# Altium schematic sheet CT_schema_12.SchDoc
size 742 x 377 mm
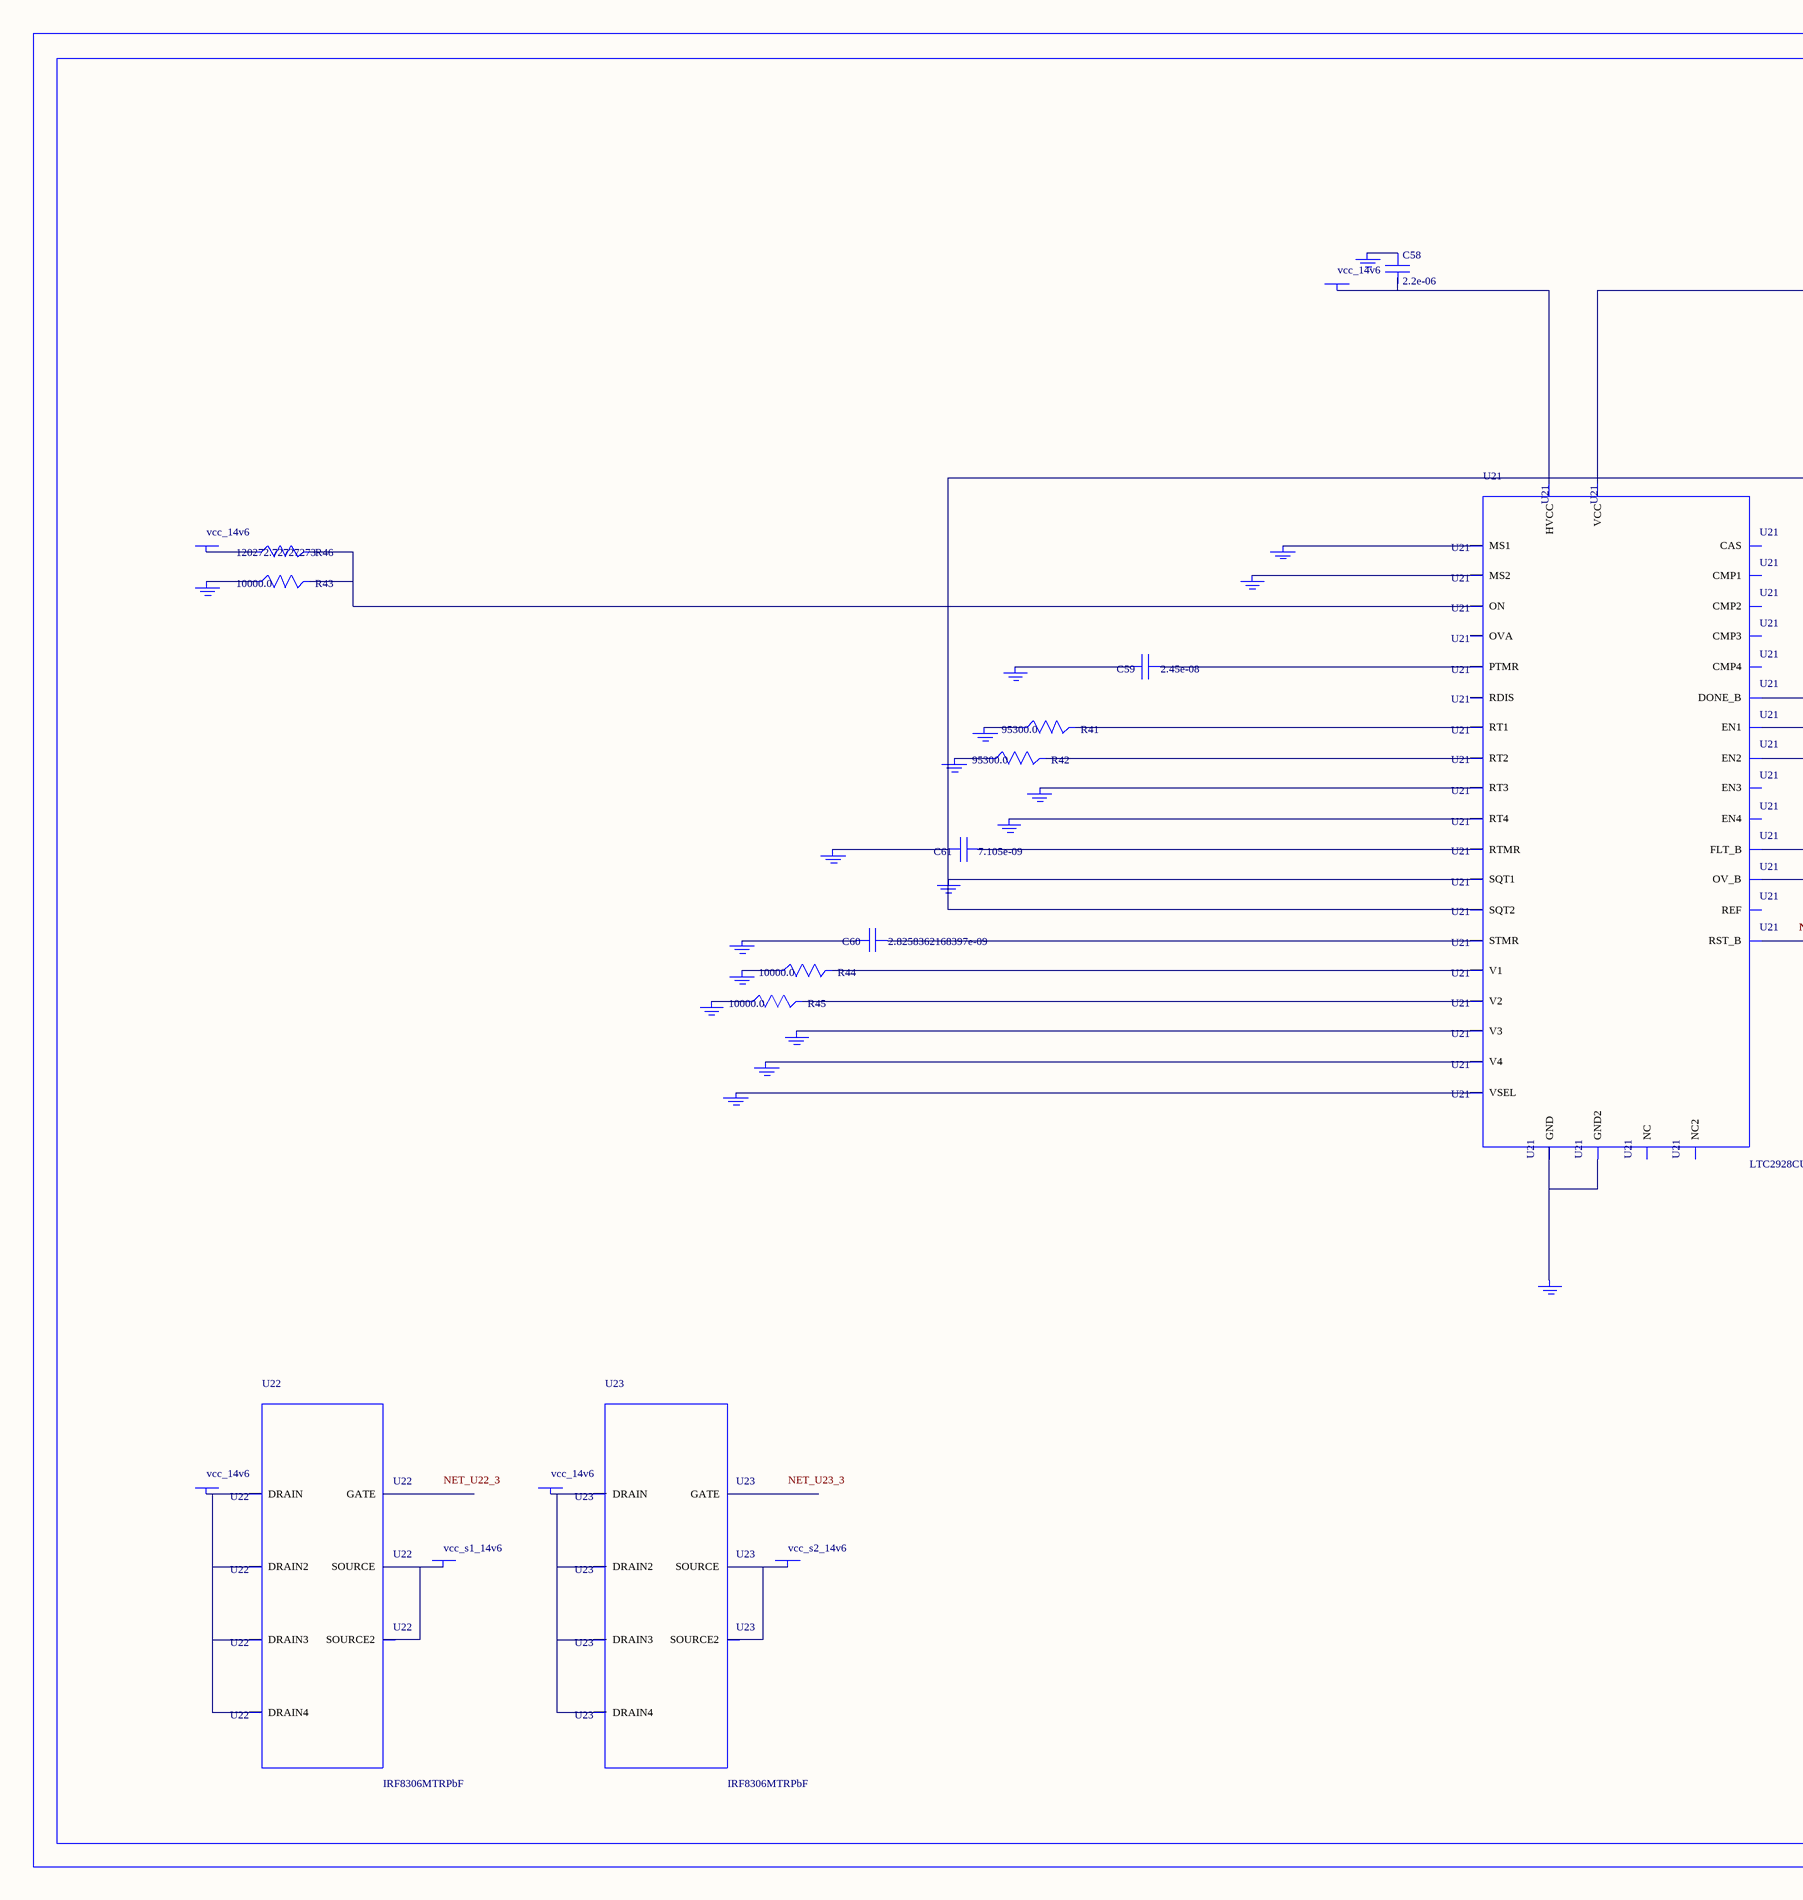
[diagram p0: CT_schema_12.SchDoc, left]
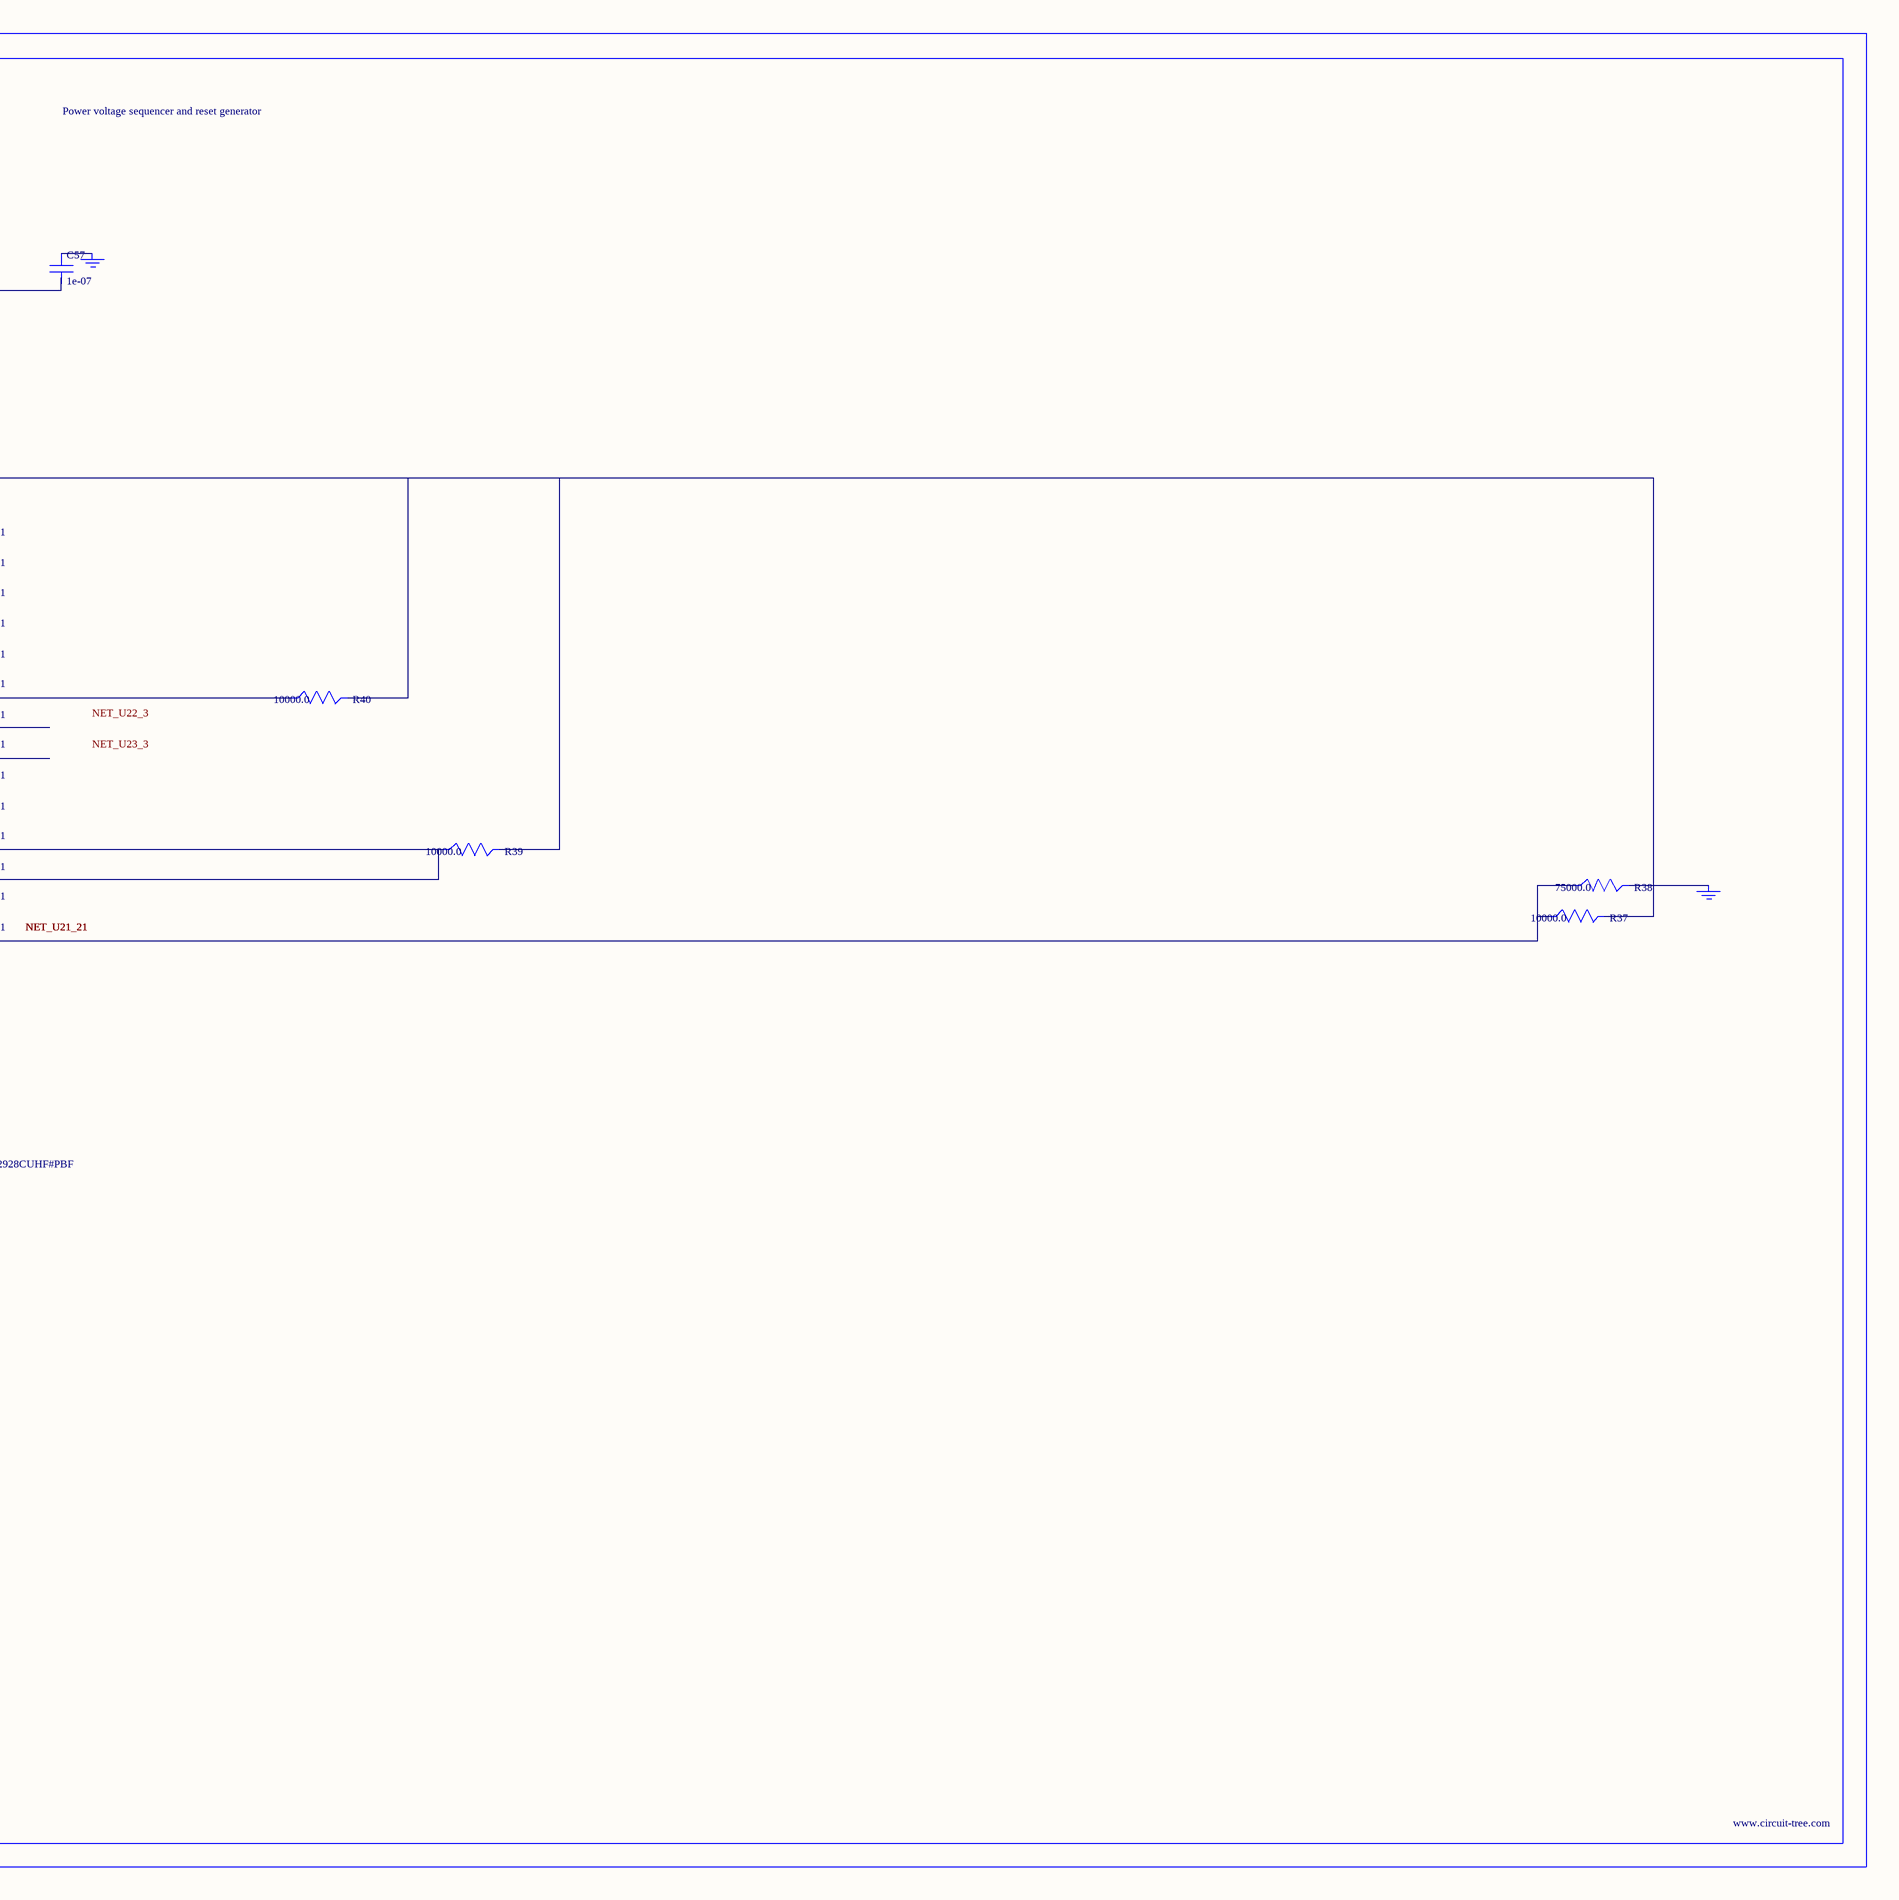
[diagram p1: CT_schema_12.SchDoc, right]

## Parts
BORDER11  (no value)
C57  1e-07  [C0402]
C58  2.2e-06  [C0603]
C59  2.45e-08  [R0603]
C60  2.8258362168397e-09  [R0603]
C61  7.105e-09  [R0603]
GND_INSTANCE_11_0  (no value)
GND_INSTANCE_11_1  (no value)
GND_INSTANCE_11_2  (no value)
GND_INSTANCE_11_3  (no value)
GND_INSTANCE_11_4  (no value)
GND_INSTANCE_11_5  (no value)
GND_INSTANCE_11_6  (no value)
GND_INSTANCE_11_7  (no value)
GND_INSTANCE_11_8  (no value)
GND_INSTANCE_11_9  (no value)
GND_INSTANCE_11_10  (no value)
GND_INSTANCE_11_11  (no value)
GND_INSTANCE_11_12  (no value)
GND_INSTANCE_11_13  (no value)
GND_INSTANCE_11_14  (no value)
GND_INSTANCE_11_15  (no value)
GND_INSTANCE_11_16  (no value)
GND_INSTANCE_11_17  (no value)
GND_INSTANCE_11_18  (no value)
GND_INSTANCE_11_19  (no value)
POWER_INSTANCE_11_0  vcc_14v6
POWER_INSTANCE_11_1  vcc_14v6
POWER_INSTANCE_11_2  vcc_14v6
POWER_INSTANCE_11_3  vcc_s1_14v6
POWER_INSTANCE_11_4  vcc_14v6
POWER_INSTANCE_11_5  vcc_s2_14v6
R37  10000.0  [R0603]
R38  75000.0  [R0603]
R39  10000.0  [R0603]
R40  10000.0  [R0603]
R41  95300.0  [R0603]
R42  95300.0  [R0603]
R43  10000.0  [R0603]
R44  10000.0  [R0603]
R45  10000.0  [R0603]
R46  120272.72727273  [R0603]
U21  LTC2928CUHF#PBF  [QFN-38_UHF]
U22  IRF8306MTRPbF  [IRF8306MTRPBF]
U23  IRF8306MTRPbF  [IRF8306MTRPBF]

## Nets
NetC57_1: C57.1 GND_INSTANCE_11_10.0(GND)
NetC57_2: C57.2 C61.2 GND_INSTANCE_11_5.0(GND) GND_INSTANCE_11_15.0(GND) R37.2 R39.2 R40.2 U21.10(SQT1) U21.11(SQT2) U21.22(VCC)
NetC58_1: C58.1 GND_INSTANCE_11_11.0(GND)
NetC58_2: C58.2 POWER_INSTANCE_11_1.0(PWR) U21.23(HVCC)
NetC59_1: C59.1 U21.27(PTMR)
NetC59_2: C59.2 GND_INSTANCE_11_14.0(GND)
NetC60_1: C60.1 U21.26(STMR)
NetC60_2: C60.2 GND_INSTANCE_11_13.0(GND)
NetC61_1: C61.1 U21.28(RTMR)
NetGND_INSTANCE_11_0_0: GND_INSTANCE_11_0.0(GND) R44.1
NetGND_INSTANCE_11_1_0: GND_INSTANCE_11_1.0(GND) R41.1
NetGND_INSTANCE_11_2_0: GND_INSTANCE_11_2.0(GND) R42.1
NetGND_INSTANCE_11_3_0: GND_INSTANCE_11_3.0(GND) U21.8(RT3)
NetGND_INSTANCE_11_4_0: GND_INSTANCE_11_4.0(GND) U21.9(RT4)
NetGND_INSTANCE_11_6_0: GND_INSTANCE_11_6.0(GND) U21.12(MS1)
NetGND_INSTANCE_11_7_0: GND_INSTANCE_11_7.0(GND) U21.13(MS2)
NetGND_INSTANCE_11_8_0: GND_INSTANCE_11_8.0(GND) R43.1
NetGND_INSTANCE_11_9_0: GND_INSTANCE_11_9.0(GND) R38.2
NetGND_INSTANCE_11_12_0: GND_INSTANCE_11_12.0(GND) U21.25(VSEL)
NetGND_INSTANCE_11_16_0: GND_INSTANCE_11_16.0(GND) U21.30(V4)
NetGND_INSTANCE_11_17_0: GND_INSTANCE_11_17.0(GND) U21.32(V3)
NetGND_INSTANCE_11_18_0: GND_INSTANCE_11_18.0(GND) R45.1
NetGND_INSTANCE_11_19_0: GND_INSTANCE_11_19.0(GND) U21.24(GND) U21.39(GND2)
NetPOWER_INSTANCE_11_0_0: POWER_INSTANCE_11_0.0(PWR) R46.1
NetPOWER_INSTANCE_11_2_0: POWER_INSTANCE_11_2.0(PWR) U22.1(DRAIN) U22.2(DRAIN2) U22.6(DRAIN3) U22.7(DRAIN4)
NetPOWER_INSTANCE_11_3_0: POWER_INSTANCE_11_3.0(PWR) U22.4(SOURCE) U22.5(SOURCE2)
NetPOWER_INSTANCE_11_4_0: POWER_INSTANCE_11_4.0(PWR) U23.1(DRAIN) U23.2(DRAIN2) U23.6(DRAIN3) U23.7(DRAIN4)
NetPOWER_INSTANCE_11_5_0: POWER_INSTANCE_11_5.0(PWR) U23.4(SOURCE) U23.5(SOURCE2)
NetR37_1: R37.1 R38.1 U21.21(RST_B)
NetR39_1: R39.1 U21.19(FLT_B) U21.20(OV_B)
NetR40_1: R40.1 U21.18(DONE_B)
NetR41_2: R41.2 U21.6(RT1)
NetR42_2: R42.2 U21.7(RT2)
NetR43_2: R43.2 R46.2 U21.16(ON)
NetR44_2: R44.2 U21.3(V1)
NetR45_2: R45.2 U21.38(V2)

Not connected (* = marked no-connect by the designer): U21 1(OVA) 2(EN1) 4(NC) 5(REF) 14(RDIS) 15(CAS) 17(NC2) 29(EN4) 31(EN3) 33(CMP3) 34(CMP4) 35(CMP1) 36(CMP2) 37(EN2); U22 3(GATE); U23 3(GATE)

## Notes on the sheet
- Labels drawn without touching a wire or pin: NET_U22_3, NET_U23_3

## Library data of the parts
BORDER11 = BORDER_PAGE11
C57 = C0402C104K3RACTU
C58 = GRM188R61H225KE1115D
C59 = C59
C60 = C60
C61 = C61
GND_INSTANCE_11_0-GND_INSTANCE_11_19 = GND
POWER_INSTANCE_11_0-POWER_INSTANCE_11_5 = PWR
R37 R39 R40 R43-R45 = RC0603JR-0710KL
R38 = RC0603JR-0775KL
R41 R42 = RC0603FR-0795K3L
R46 = R46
